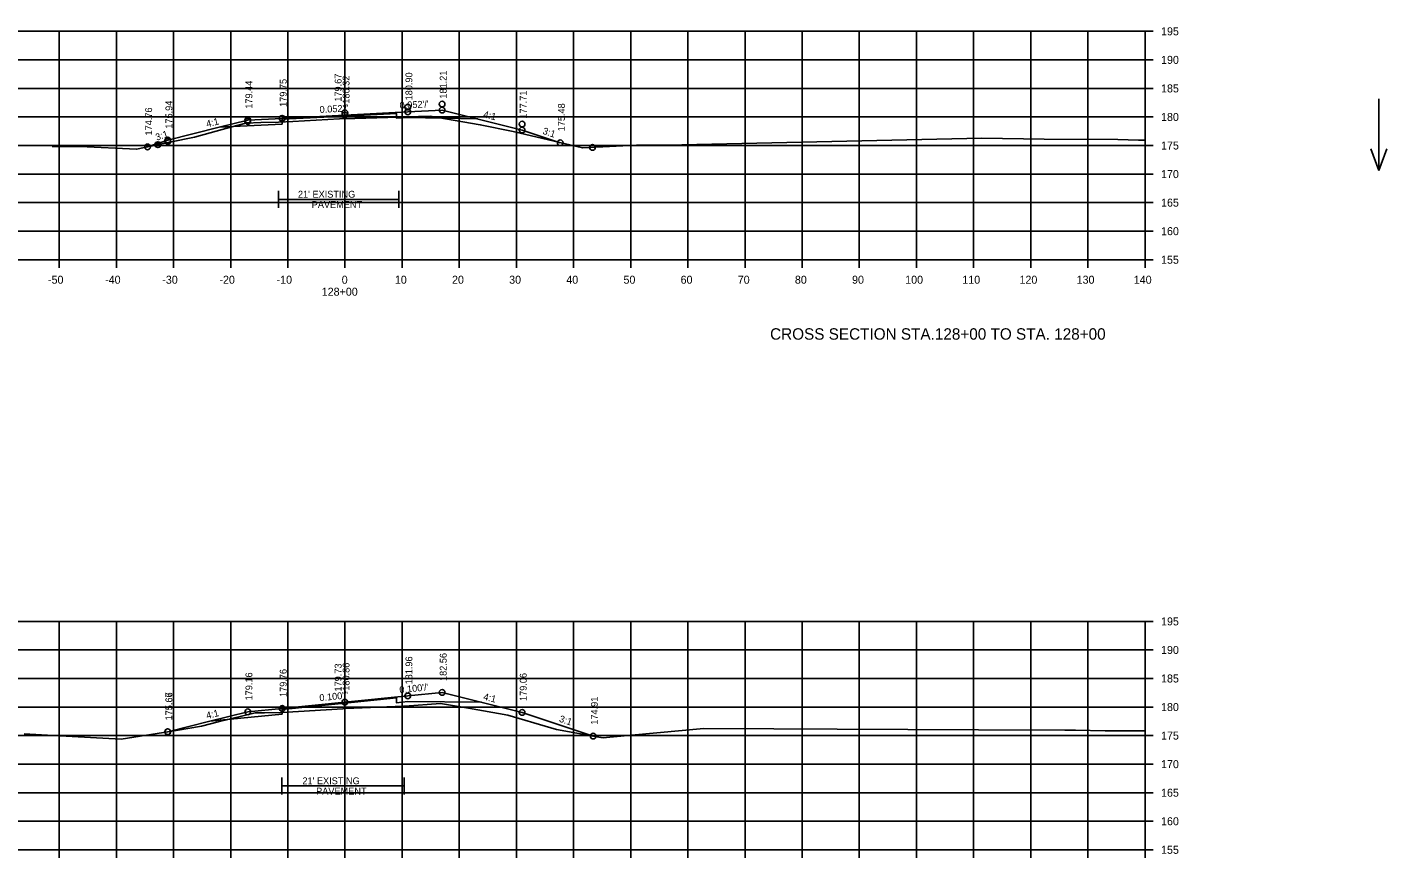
# Model space of a CAD drawing. Extents: x 915787 to 919910, y 133456 to 136717.
# Drawn here: x 916358.4 to 916596.3, y 136571.3 to 136716.8 of the extents above; entities that cross this region are included whole.
import ezdxf

# ---------------------------------------------------------------- set-up
doc = ezdxf.new("R2010")
doc.units = 0
for name, color, linetype in [('R_Axis', 7, 'Continuous'), ('R_Axis Annot', 7, 'Continuous'), ('R_Draft', 7, 'Continuous'), ('R_Exist Surface', 7, 'Continuous'), ('R_Exist Surface Annot', 7, 'Continuous'), ('R_Grid', 7, 'Continuous'), ('R_No Plot', 7, 'Continuous'), ('R_Water Annot', 7, 'Continuous')]:
    doc.layers.add(name, color=color, linetype=linetype)

msp = doc.modelspace()

# ---------------------------------------------------------------- linework, layer by layer
at = {"layer": 'R_Axis'}
for p, q in [((916553.98, 136676.08), (916553.98, 136716.08)), ((916555.38, 136716.08), (916553.98, 136716.08)), ((916555.38, 136711.08), (916553.98, 136711.08)), ((916555.38, 136706.08), (916553.98, 136706.08)), ((916555.38, 136701.08), (916553.98, 136701.08)), ((916555.38, 136696.08), (916553.98, 136696.08)), ((916555.38, 136691.08), (916553.98, 136691.08)), ((916555.38, 136686.08), (916553.98, 136686.08)), ((916555.38, 136681.08), (916553.98, 136681.08)), ((916273.98, 136676.08), (916553.98, 136676.08)), ((916363.98, 136674.68), (916363.98, 136676.08)), ((916373.98, 136674.68), (916373.98, 136676.08)), ((916383.98, 136674.68), (916383.98, 136676.08)), ((916393.98, 136674.68), (916393.98, 136676.08)), ((916403.98, 136674.68), (916403.98, 136676.08)), ((916413.98, 136674.68), (916413.98, 136676.08)), ((916423.98, 136674.68), (916423.98, 136676.08)), ((916433.98, 136674.68), (916433.98, 136676.08)), ((916443.98, 136674.68), (916443.98, 136676.08)), ((916453.98, 136674.68), (916453.98, 136676.08)), ((916463.98, 136674.68), (916463.98, 136676.08)), ((916473.98, 136674.68), (916473.98, 136676.08)), ((916483.98, 136674.68), (916483.98, 136676.08)), ((916493.98, 136674.68), (916493.98, 136676.08)), ((916503.98, 136674.68), (916503.98, 136676.08)), ((916513.98, 136674.68), (916513.98, 136676.08)), ((916523.98, 136674.68), (916523.98, 136676.08)), ((916533.98, 136674.68), (916533.98, 136676.08)), ((916543.98, 136674.68), (916543.98, 136676.08)), ((916553.98, 136674.68), (916553.98, 136676.08)), ((916555.38, 136676.08), (916553.98, 136676.08)), ((916553.98, 136572.75), (916553.98, 136612.75)), ((916555.38, 136612.75), (916553.98, 136612.75)), ((916555.38, 136607.75), (916553.98, 136607.75)), ((916555.38, 136602.75), (916553.98, 136602.75)), ((916555.38, 136597.75), (916553.98, 136597.75)), ((916555.38, 136592.75), (916553.98, 136592.75)), ((916555.38, 136587.75), (916553.98, 136587.75)), ((916555.38, 136582.75), (916553.98, 136582.75)), ((916555.38, 136577.75), (916553.98, 136577.75)), ((916273.98, 136572.75), (916553.98, 136572.75)), ((916363.98, 136571.35), (916363.98, 136572.75)), ((916373.98, 136571.35), (916373.98, 136572.75)), ((916383.98, 136571.35), (916383.98, 136572.75)), ((916393.98, 136571.35), (916393.98, 136572.75)), ((916403.98, 136571.35), (916403.98, 136572.75)), ((916413.98, 136571.35), (916413.98, 136572.75)), ((916423.98, 136571.35), (916423.98, 136572.75)), ((916433.98, 136571.35), (916433.98, 136572.75)), ((916443.98, 136571.35), (916443.98, 136572.75)), ((916453.98, 136571.35), (916453.98, 136572.75)), ((916463.98, 136571.35), (916463.98, 136572.75)), ((916473.98, 136571.35), (916473.98, 136572.75)), ((916483.98, 136571.35), (916483.98, 136572.75)), ((916493.98, 136571.35), (916493.98, 136572.75)), ((916503.98, 136571.35), (916503.98, 136572.75)), ((916513.98, 136571.35), (916513.98, 136572.75)), ((916523.98, 136571.35), (916523.98, 136572.75)), ((916533.98, 136571.35), (916533.98, 136572.75)), ((916543.98, 136571.35), (916543.98, 136572.75)), ((916553.98, 136571.35), (916553.98, 136572.75)), ((916555.38, 136572.75), (916553.98, 136572.75))]:
    msp.add_line(p, q, dxfattribs=at)
at = {"layer": 'R_Exist Surface'}
for points in [[(916362.73, 136695.9), (916363.39, 136695.9), (916367.62, 136695.91), (916377.52, 136695.44), (916383.32, 136696.66), (916387.67, 136697.54), (916394.18, 136699.33), (916396.64, 136700.01), (916399.27, 136700.09), (916402.35, 136700.17), (916404.86, 136700.3), (916413, 136700.73), (916415.72, 136700.81), (916423.4, 136701.03), (916424.82, 136701.09), (916428.9, 136701.22), (916437.65, 136699.73), (916443.43, 136698.51), (916455.52, 136695.66), (916465.01, 136696.12), (916470.31, 136696.14), (916525.43, 136697.34), (916536.35, 136697.22), (916549.23, 136697.13), (916552.82, 136697.03), (916553.98, 136697.03)], [(916357.82, 136593.07), (916360.85, 136592.87), (916374.83, 136592.14), (916384.43, 136593.65), (916388.88, 136594.43), (916391.81, 136595.15), (916398.24, 136596.71), (916399.91, 136596.73), (916402.95, 136596.8), (916413.59, 136597.45), (916414.08, 136597.48), (916424.22, 136597.89), (916424.34, 136597.89), (916424.43, 136597.9), (916430.71, 136598.36), (916435.6, 136597.53), (916442.46, 136596.35), (916450, 136594.11), (916451.01, 136593.81), (916458.77, 136592.42), (916459.16, 136592.35), (916460.32, 136592.46), (916476.79, 136594), (916489.04, 136593.93), (916500.08, 136593.87), (916524.84, 136593.77), (916539.94, 136593.71), (916541.83, 136593.68), (916546.99, 136593.56), (916553.98, 136593.58)]]:
    msp.add_lwpolyline(points, dxfattribs=at)
at = {"layer": 'R_Exist Surface Annot'}
for p, q in [((916402.35, 136688.15), (916402.35, 136685.15)), ((916402.35, 136686.65), (916423.4, 136686.65)), ((916423.4, 136688.15), (916423.4, 136685.15)), ((916402.95, 136585.43), (916402.95, 136582.43)), ((916402.95, 136583.93), (916424.34, 136583.93)), ((916424.34, 136585.43), (916424.34, 136582.43))]:
    msp.add_line(p, q, dxfattribs=at)
at = {"layer": 'R_Grid'}
for p, q in [((916273.98, 136716.08), (916553.98, 136716.08)), ((916273.98, 136716.08), (916553.98, 136716.08)), ((916363.98, 136676.08), (916363.98, 136716.08)), ((916363.98, 136676.08), (916363.98, 136716.08)), ((916373.98, 136676.08), (916373.98, 136716.08)), ((916373.98, 136676.08), (916373.98, 136716.08)), ((916383.98, 136676.08), (916383.98, 136716.08)), ((916383.98, 136676.08), (916383.98, 136716.08)), ((916393.98, 136676.08), (916393.98, 136716.08)), ((916393.98, 136676.08), (916393.98, 136716.08)), ((916403.98, 136676.08), (916403.98, 136716.08)), ((916403.98, 136676.08), (916403.98, 136716.08)), ((916413.98, 136676.08), (916413.98, 136716.08)), ((916413.98, 136676.08), (916413.98, 136716.08)), ((916423.98, 136676.08), (916423.98, 136716.08)), ((916423.98, 136676.08), (916423.98, 136716.08)), ((916433.98, 136676.08), (916433.98, 136716.08)), ((916433.98, 136676.08), (916433.98, 136716.08)), ((916443.98, 136676.08), (916443.98, 136716.08)), ((916443.98, 136676.08), (916443.98, 136716.08)), ((916453.98, 136676.08), (916453.98, 136716.08)), ((916453.98, 136676.08), (916453.98, 136716.08)), ((916463.98, 136676.08), (916463.98, 136716.08)), ((916463.98, 136676.08), (916463.98, 136716.08)), ((916473.98, 136676.08), (916473.98, 136716.08)), ((916473.98, 136676.08), (916473.98, 136716.08)), ((916483.98, 136676.08), (916483.98, 136716.08)), ((916483.98, 136676.08), (916483.98, 136716.08)), ((916493.98, 136676.08), (916493.98, 136716.08)), ((916493.98, 136676.08), (916493.98, 136716.08)), ((916503.98, 136676.08), (916503.98, 136716.08)), ((916503.98, 136676.08), (916503.98, 136716.08)), ((916513.98, 136676.08), (916513.98, 136716.08)), ((916513.98, 136676.08), (916513.98, 136716.08)), ((916523.98, 136676.08), (916523.98, 136716.08)), ((916523.98, 136676.08), (916523.98, 136716.08)), ((916533.98, 136676.08), (916533.98, 136716.08)), ((916533.98, 136676.08), (916533.98, 136716.08)), ((916543.98, 136676.08), (916543.98, 136716.08)), ((916543.98, 136676.08), (916543.98, 136716.08)), ((916553.98, 136676.08), (916553.98, 136716.08)), ((916553.98, 136676.08), (916553.98, 136716.08)), ((916273.98, 136711.08), (916553.98, 136711.08)), ((916273.98, 136711.08), (916553.98, 136711.08)), ((916273.98, 136706.08), (916553.98, 136706.08)), ((916273.98, 136706.08), (916553.98, 136706.08)), ((916273.98, 136701.08), (916553.98, 136701.08)), ((916273.98, 136701.08), (916553.98, 136701.08)), ((916273.98, 136696.08), (916553.98, 136696.08)), ((916273.98, 136696.08), (916553.98, 136696.08)), ((916273.98, 136691.08), (916553.98, 136691.08)), ((916273.98, 136691.08), (916553.98, 136691.08)), ((916273.98, 136686.08), (916553.98, 136686.08)), ((916273.98, 136686.08), (916553.98, 136686.08)), ((916273.98, 136681.08), (916553.98, 136681.08)), ((916273.98, 136681.08), (916553.98, 136681.08)), ((916273.98, 136676.08), (916553.98, 136676.08)), ((916273.98, 136676.08), (916553.98, 136676.08)), ((916273.98, 136612.75), (916553.98, 136612.75)), ((916363.98, 136572.75), (916363.98, 136612.75)), ((916373.98, 136572.75), (916373.98, 136612.75)), ((916383.98, 136572.75), (916383.98, 136612.75)), ((916393.98, 136572.75), (916393.98, 136612.75)), ((916403.98, 136572.75), (916403.98, 136612.75)), ((916413.98, 136572.75), (916413.98, 136612.75)), ((916423.98, 136572.75), (916423.98, 136612.75)), ((916433.98, 136572.75), (916433.98, 136612.75)), ((916443.98, 136572.75), (916443.98, 136612.75)), ((916453.98, 136572.75), (916453.98, 136612.75)), ((916463.98, 136572.75), (916463.98, 136612.75)), ((916473.98, 136572.75), (916473.98, 136612.75)), ((916483.98, 136572.75), (916483.98, 136612.75)), ((916493.98, 136572.75), (916493.98, 136612.75)), ((916503.98, 136572.75), (916503.98, 136612.75)), ((916513.98, 136572.75), (916513.98, 136612.75)), ((916523.98, 136572.75), (916523.98, 136612.75)), ((916533.98, 136572.75), (916533.98, 136612.75)), ((916543.98, 136572.75), (916543.98, 136612.75)), ((916553.98, 136572.75), (916553.98, 136612.75)), ((916273.98, 136607.75), (916553.98, 136607.75)), ((916273.98, 136602.75), (916553.98, 136602.75)), ((916273.98, 136597.75), (916553.98, 136597.75)), ((916273.98, 136592.75), (916553.98, 136592.75)), ((916273.98, 136587.75), (916553.98, 136587.75)), ((916273.98, 136582.75), (916553.98, 136582.75)), ((916273.98, 136577.75), (916553.98, 136577.75)), ((916273.98, 136572.75), (916553.98, 136572.75))]:
    msp.add_line(p, q, dxfattribs=at)
at = {"layer": 'R_No Plot'}
for points in [[(916379.43, 136695.84), (916382.97, 136697.03), (916391.94, 136699.27), (916396.97, 136700.53), (916402.97, 136700.84), (916413.97, 136701.41), (916424.97, 136701.98), (916430.97, 136702.29), (916444.97, 136698.79), (916451.65, 136696.57)], [(916391.94, 136699.27), (916402.98, 136699.84), (916402.97, 136700.67), (916413.97, 136701.24), (916422.97, 136701.71), (916422.98, 136700.88), (916424.98, 136700.98), (916437.2, 136700.74)], [(916382.95, 136593.42), (916382.97, 136593.41), (916390.33, 136595.25), (916396.97, 136596.91), (916402.97, 136597.51), (916413.97, 136598.61), (916424.97, 136599.71), (916430.97, 136600.31), (916444.97, 136596.81), (916457.42, 136592.66)], [(916390.33, 136595.25), (916402.98, 136596.51), (916402.97, 136597.34), (916413.97, 136598.44), (916422.97, 136599.34), (916422.98, 136598.51), (916424.98, 136598.71), (916437.87, 136598.59)]]:
    msp.add_lwpolyline(points, dxfattribs=at)
for centre in [(916424.97, 136702.81), (916430.97, 136703.34), (916430.97, 136702.29), (916396.97, 136700.53), (916396.97, 136700.3), (916402.97, 136700.84), (916402.97, 136700.84), (916413.97, 136701.82), (916413.97, 136701.41), (916424.97, 136701.98), (916444.97, 136699.84), (916444.97, 136698.79), (916379.43, 136695.84), (916381.25, 136696.23), (916382.97, 136697.03), (916382.97, 136696.8), (916451.65, 136696.57), (916457.28, 136695.74), (916430.97, 136600.31), (916430.97, 136600.31), (916402.97, 136597.51), (916402.97, 136597.51), (916413.97, 136598.61), (916413.97, 136598.61), (916424.97, 136599.71), (916424.97, 136599.71), (916396.97, 136596.91), (916396.97, 136596.91), (916444.97, 136596.81), (916444.97, 136596.81), (916382.95, 136593.42), (916382.95, 136593.42), (916382.95, 136593.42), (916382.95, 136593.42), (916382.97, 136593.41), (916382.97, 136593.41), (916457.42, 136592.66), (916457.42, 136592.66)]:
    msp.add_circle(centre, 0.5, dxfattribs=at)
at = {"layer": 'R_Water Annot'}
for p, q in [((916594.88, 136704.25), (916594.88, 136691.68)), ((916594.88, 136691.68), (916593.48, 136695.53)), ((916594.88, 136691.68), (916596.28, 136695.53))]:
    msp.add_line(p, q, dxfattribs=at)

# ---------------------------------------------------------------- texts
at = {"layer": 'R_Axis Annot'}
for s, p in [('195', (916556.78, 136715.38)), ('190', (916556.78, 136710.38)), ('185', (916556.78, 136705.38)), ('180', (916556.78, 136700.38)), ('175', (916556.78, 136695.38)), ('170', (916556.78, 136690.38)), ('165', (916556.78, 136685.38)), ('160', (916556.78, 136680.38)), ('155', (916556.78, 136675.38)), ('-50', (916362.01, 136671.88)), ('-40', (916372.01, 136671.88)), ('-30', (916382.01, 136671.88)), ('-20', (916392.01, 136671.88)), ('-10', (916402.01, 136671.88)), ('0', (916413.41, 136671.88)), ('10', (916422.71, 136671.88)), ('20', (916432.71, 136671.88)), ('30', (916442.71, 136671.88)), ('40', (916452.71, 136671.88)), ('50', (916462.71, 136671.88)), ('60', (916472.71, 136671.88)), ('70', (916482.71, 136671.88)), ('80', (916492.71, 136671.88)), ('90', (916502.71, 136671.88)), ('100', (916512.01, 136671.88)), ('110', (916522.01, 136671.88)), ('120', (916532.01, 136671.88)), ('130', (916542.01, 136671.88)), ('140', (916552.01, 136671.88)), ('128+00', (916409.91, 136669.78)), ('195', (916556.78, 136612.05)), ('190', (916556.78, 136607.05)), ('185', (916556.78, 136602.05)), ('180', (916556.78, 136597.05)), ('175', (916556.78, 136592.05)), ('170', (916556.78, 136587.05)), ('165', (916556.78, 136582.05)), ('160', (916556.78, 136577.05)), ('155', (916556.78, 136572.05))]:
    msp.add_text(s, height=1.4, dxfattribs=at).set_placement(p)
at = {"layer": 'R_Draft'}
msp.add_text('CROSS SECTION STA.128+00 TO STA. 128+00', height=2, dxfattribs=at).set_placement((916488.37, 136662.08))
at = {"layer": 'R_Exist Surface Annot'}
for s, p in [("21' EXISTING", (916405.75, 136686.95)), ('PAVEMENT', (916408.16, 136685.15)), ("21' EXISTING", (916406.53, 136584.23)), ('PAVEMENT', (916408.93, 136582.43))]:
    msp.add_text(s, height=1.2, dxfattribs=at).set_placement(p)
at = {"layer": 'R_No Plot'}
for s, rotation, p in [('179.44', 90, (916397.77, 136702.53)), ('179.75', 90, (916403.77, 136702.84)), ('179.67', 90, (916413.38, 136703.76)), ('180.32', 90, (916414.77, 136703.41)), ('180.90', 90, (916425.77, 136703.98)), ('181.21', 90, (916431.77, 136704.29)), ('177.71', 90, (916445.77, 136700.79)), ('174.76', 90, (916380.23, 136697.84)), ('175.94', 90, (916383.77, 136699.03)), ("0.052'/'", 2.9761, (916409.57, 136701.78)), ("0.052'/'", 2.9767, (916423.57, 136702.51)), ('175.48', 90, (916452.45, 136698.57)), ('4:1', 14.0362, (916389.85, 136699.26)), ('4:1', 345.9638, (916438.1, 136701.03)), ('3:1', 18.4349, (916381.04, 136696.91)), ('3:1', 341.5651, (916448.47, 136698.15)), ('179.73', 90, (916413.38, 136600.47)), ('180.86', 90, (916414.77, 136600.61)), ('181.96', 90, (916425.77, 136601.71)), ('182.56', 90, (916431.77, 136602.31)), ('179.16', 90, (916397.77, 136598.91)), ('179.76', 90, (916403.77, 136599.51)), ('179.06', 90, (916445.77, 136598.81)), ("0.100'/'", 5.7106, (916409.56, 136598.77)), ("0.100'/'", 5.7106, (916423.56, 136600.17)), ('175.67', 90, (916383.75, 136595.42)), ('175.66', 90, (916383.77, 136595.41)), ('4:1', 345.9638, (916438.1, 136599.05)), ('174.91', 90, (916458.22, 136594.66)), ('4:1', 14.0362, (916389.85, 136595.65)), ('3:1', 341.5651, (916451.36, 136595.21))]:
    msp.add_text(s, height=1.2, rotation=rotation, dxfattribs=at).set_placement(p)

doc.saveas('drawing.dxf')
